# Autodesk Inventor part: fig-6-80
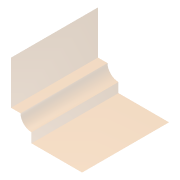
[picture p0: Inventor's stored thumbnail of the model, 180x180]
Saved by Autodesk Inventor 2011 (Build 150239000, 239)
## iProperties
Shininess: 64.0
Length Units: 11269
Angle Units: 11279
Time Units: 11290
Mass Units: 11283
Length Display Precision: 3
Angle Display Precision: 2
Compacted: True
Part Number: fig-6-80
Document SubType Name: Modeling
Created: 2003-10
Designer: Owner
Manufacturer: Standard
Standards Organization: Custom
Density: 1 g/cm^3
Density: 0.0
Volumn: 0.0
Area: 0.0
PropertySet Name: Model Information
Control State: 0
Master: False
Checked Out: False
Author: Owner
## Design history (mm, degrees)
node "Sketch1"
sketch "Sketch2"
  geometry: L1 (22.777, 31.862)-(22.777, 0.2); L2 (7.777, -14.8)-(-29.161, -14.8); A1 r 15 centre (7.777, 0.2) between (7.777, -14.8) and (22.777, 0.2)
  constraints: 4 end point, 2 point on circle, 2 tangent, 1 centre point, 1 perpendicular, 1 vertical
  dimensions: "d23" = 15 radius of A1
extrude_surface "ExtrusionSrf1" sketch "Sketch2" dims "d24" = 63.5, "d25" = 0
feature "OffsetSrf12" dims "d31" = 7, "d32" = 1
body "Solid1"
body "Srf1"
